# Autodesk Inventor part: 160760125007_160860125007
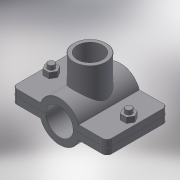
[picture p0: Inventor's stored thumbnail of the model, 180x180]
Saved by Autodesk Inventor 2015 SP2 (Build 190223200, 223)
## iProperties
Created: 2017-05
Part Number: 160760125007_160860125007
Material: Generic
Description: PLASSON SADDLE 125-3/4"
Document SubType Name: Modeling
Designer: KIM
Density: 1 g/cm^3
Appearance: Default
Author: KIM
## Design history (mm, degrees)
derived "16076.ipt"
feature "Solid1::16076.ipt"
feature "Solid2::16076.ipt"
tag "TaggingFeature1"
body "Solid1"
other parameters: "d0" = 137.5, "d1" = 184, "d2" = 62.5, "d3" = 125, "d4" = 124, "d5" = 0, "d6" = 9.2, "d7" = 184, "d8" = 0.1, "d10" = 0, "d11" = 1.25, "d14" = 31.3521, "d20" = 1.25, "d23" = 1.25, "d36" = 13, "d37" = 10.4, "d38" = 70.5, "d39" = 0, "d40" = 3, "d41" = 5, "d42" = 0, "d43" = 8, "d44" = 3, "d45" = 0, "d46" = 1.25, "d51" = 91, "d52" = 24.117, "d53" = 19, "d54" = 0, "d57" = 0, "d58" = 135, "d60" = 0, "d62" = 13, "d63" = 10.4, "d66" = 103.2, "d_" = 125, "G_" = 24.117, "A_" = 91, "L_" = 184, "L_1" = 124, "l_2" = 19
